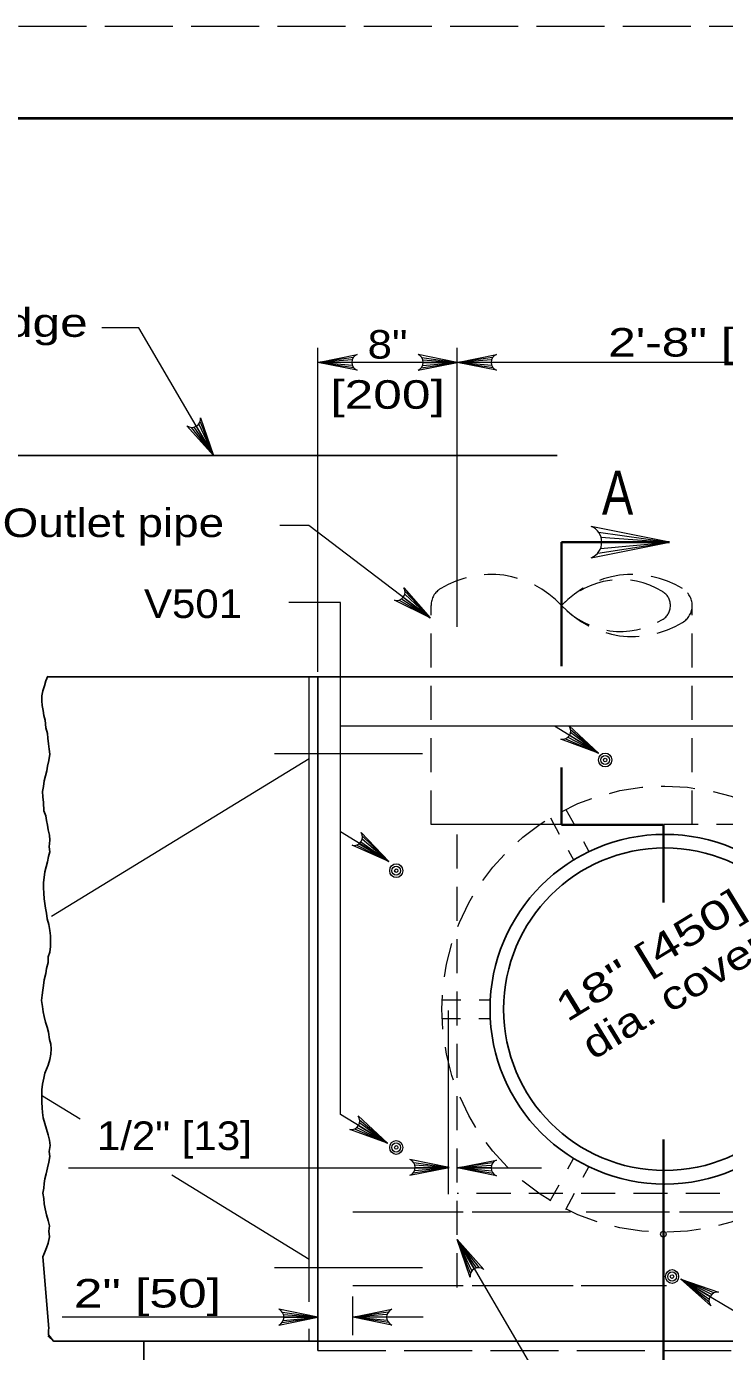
# Model space of a CAD drawing. Extents: x 339.1 to 373.1, y 1412.7 to 1456.7.
# Drawn here: x 343.47 to 347.29, y 1449.51 to 1456.75 of the extents above; entities that cross this region are included whole.
import ezdxf
from ezdxf.enums import TextEntityAlignment as Align

# ---------------------------------------------------------------- set-up
doc = ezdxf.new("R2010")
doc.units = 0
doc.header["$LTSCALE"] = 0.062
doc.header["$PDMODE"] = 32
doc.header["$PDSIZE"] = 0.031
for name, pattern in [('DOTTED', [1.5, 0.3, -1.2]), ('LONG_DASHED', [7.5, 6, -1.5]), ('MEDIUM_DASHED', [4.5, 3, -1.5])]:
    doc.linetypes.add(name, pattern=pattern)
doc.layers.add('1', color=7, linetype='Continuous', lineweight=13)

msp = doc.modelspace()

# ---------------------------------------------------------------- linework, layer by layer
at = {"layer": '1', "lineweight": 25}
for p, q in [((341.0605, 1456.2455), (372.5605, 1456.2455)), ((346.37042, 1454.40183), (342.06367, 1454.40183)), ((345.06217, 1449.51425), (345.06217, 1453.1925)), ((343.55767, 1450.0245), (343.59117, 1449.63442)), ((360.97275, 1449.56467), (343.61608, 1449.56467)), ((344.11025, 1447.75067), (344.11025, 1449.56467))]:
    msp.add_line(p, q, dxfattribs=at)
at = {"layer": '1'}
for p, q in [((345.06217, 1453.22042), (345.06217, 1454.9895)), ((345.25608, 1454.938), (345.06217, 1454.91083)), ((345.62975, 1454.938), (345.82367, 1454.91083)), ((345.82367, 1453.46592), (345.82367, 1454.9895)), ((346.0175, 1454.938), (345.82367, 1454.91083)), ((345.2495, 1454.92458), (345.06217, 1454.91083)), ((345.30475, 1454.91083), (345.06217, 1454.91083)), ((345.2475, 1454.91083), (345.06217, 1454.91083)), ((345.25092, 1454.89342), (345.06217, 1454.91083)), ((345.25833, 1454.88092), (345.06217, 1454.91083)), ((345.82367, 1454.91083), (345.30475, 1454.91083)), ((345.6275, 1454.88092), (345.82367, 1454.91083)), ((345.63492, 1454.89342), (345.82367, 1454.91083)), ((345.63633, 1454.92458), (345.82367, 1454.91083)), ((345.63833, 1454.91083), (345.82367, 1454.91083)), ((346.011, 1454.92458), (345.82367, 1454.91083)), ((347.44108, 1454.91083), (345.82367, 1454.91083)), ((346.009, 1454.91083), (345.82367, 1454.91083)), ((346.01242, 1454.89342), (345.82367, 1454.91083)), ((346.01983, 1454.88092), (345.82367, 1454.91083)), ((344.41067, 1454.5735), (344.491, 1454.40183)), ((344.41775, 1454.58625), (344.491, 1454.40183)), ((344.36967, 1454.55542), (344.491, 1454.40183)), ((344.3845, 1454.55658), (344.491, 1454.40183)), ((344.39742, 1454.56175), (344.491, 1454.40183)), ((346.59217, 1453.86925), (346.9845, 1453.92917)), ((346.59675, 1453.9835), (346.9845, 1453.92917)), ((346.607, 1453.89433), (346.9845, 1453.92917)), ((346.60983, 1453.95658), (346.9845, 1453.92917)), ((346.61383, 1453.92917), (346.9845, 1453.92917)), ((345.52908, 1453.62817), (345.67608, 1453.51533)), ((345.537, 1453.64408), (345.67608, 1453.51533)), ((345.53875, 1453.65858), (345.67608, 1453.51533)), ((345.50575, 1453.61183), (345.67608, 1453.51533)), ((345.51917, 1453.6185), (345.67608, 1453.51533)), ((345.01458, 1449.779), (345.01458, 1453.1925)), ((347.8135, 1452.92358), (345.18583, 1452.92358)), ((346.59558, 1452.77717), (346.35608, 1452.92358)), ((346.44383, 1452.90508), (346.59558, 1452.77717)), ((346.416, 1452.85517), (346.59558, 1452.77717)), ((346.42867, 1452.86317), (346.59558, 1452.77717)), ((346.4375, 1452.87383), (346.59558, 1452.77717)), ((346.44367, 1452.8905), (346.59558, 1452.77717)), ((344.82417, 1452.77517), (345.63325, 1452.77517)), ((345.01458, 1452.74608), (343.60592, 1451.885)), ((345.4495, 1452.18542), (345.18583, 1452.34658)), ((345.27508, 1452.27442), (345.4495, 1452.18542)), ((345.28817, 1452.28167), (345.4495, 1452.18542)), ((345.29767, 1452.29175), (345.4495, 1452.18542)), ((345.30492, 1452.308), (345.4495, 1452.18542)), ((345.306, 1452.3225), (345.4495, 1452.18542)), ((345.77483, 1451.37017), (345.77483, 1450.3675)), ((343.762, 1450.77708), (343.55583, 1450.90317)), ((345.442, 1450.64625), (345.18583, 1450.80292)), ((345.27508, 1450.73225), (345.442, 1450.64625)), ((345.28392, 1450.74292), (345.442, 1450.64625)), ((345.29008, 1450.75958), (345.442, 1450.64625)), ((345.29033, 1450.77417), (345.442, 1450.64625)), ((345.2625, 1450.72425), (345.442, 1450.64625)), ((345.58583, 1450.5405), (345.77975, 1450.51333)), ((345.59242, 1450.52708), (345.77975, 1450.51333)), ((346.0175, 1450.53833), (345.82367, 1450.51125)), ((346.011, 1450.52492), (345.82367, 1450.51125)), ((343.69883, 1450.51125), (345.77608, 1450.51125)), ((345.01458, 1450.01133), (344.26333, 1450.47058)), ((345.58358, 1450.48333), (345.77975, 1450.51333)), ((345.591, 1450.49592), (345.77975, 1450.51333)), ((345.59442, 1450.51333), (345.77975, 1450.51333)), ((345.82367, 1450.51125), (346.28475, 1450.51125)), ((346.009, 1450.51125), (345.82367, 1450.51125)), ((346.01242, 1450.49383), (345.82367, 1450.51125)), ((346.01983, 1450.48125), (345.82367, 1450.51125)), ((345.85683, 1450.27008), (345.2525, 1450.27008)), ((346.44342, 1450.27008), (345.90608, 1450.27008)), ((346.98492, 1450.26933), (346.52825, 1450.26933)), ((347.58933, 1450.26933), (347.03867, 1450.26933)), ((345.91717, 1449.95967), (345.82367, 1450.11967)), ((345.90383, 1449.94792), (345.82367, 1450.11967)), ((345.89675, 1449.93517), (345.82367, 1450.11967)), ((345.93, 1449.96483), (345.82367, 1450.11967)), ((345.94492, 1449.966), (345.82367, 1450.11967)), ((344.82417, 1449.96775), (345.63325, 1449.96775)), ((345.85683, 1449.86692), (345.2525, 1449.86692)), ((346.45683, 1449.86692), (345.90608, 1449.86692)), ((346.96725, 1449.86692), (346.50158, 1449.86692)), ((347.0465, 1449.903), (348.2655, 1449.18067)), ((347.20642, 1449.80933), (347.0465, 1449.903)), ((347.20058, 1449.79258), (347.0465, 1449.903)), ((347.20058, 1449.778), (347.0465, 1449.903)), ((347.21508, 1449.82017), (347.0465, 1449.903)), ((347.2275, 1449.82842), (347.0465, 1449.903)), ((345.2525, 1449.5975), (345.2525, 1449.80892)), ((344.86825, 1449.72275), (345.06217, 1449.69567)), ((345.44642, 1449.72275), (345.2525, 1449.69567)), ((345.06217, 1449.69567), (343.66375, 1449.69567)), ((344.866, 1449.66567), (345.06217, 1449.69567)), ((344.87342, 1449.67825), (345.06217, 1449.69567)), ((344.87483, 1449.70933), (345.06217, 1449.69567)), ((344.87683, 1449.69567), (345.06217, 1449.69567)), ((345.43983, 1449.70933), (345.2525, 1449.69567)), ((345.63683, 1449.69567), (345.2525, 1449.69567)), ((345.43783, 1449.69567), (345.2525, 1449.69567)), ((345.44125, 1449.67825), (345.2525, 1449.69567)), ((345.44867, 1449.66567), (345.2525, 1449.69567)), ((345.01458, 1449.56467), (345.01458, 1449.63208))]:
    msp.add_line(p, q, dxfattribs=at)
at = {"layer": '1', "lineweight": 35}
for p, q in [((346.39475, 1453.92917), (346.9845, 1453.92917)), ((346.39475, 1453.92917), (346.39475, 1453.71192)), ((346.39475, 1453.90008), (346.39475, 1453.71467)), ((346.39475, 1453.87417), (346.39475, 1453.8635)), ((346.39475, 1453.71192), (346.39475, 1453.25158)), ((346.39475, 1452.6985), (346.39475, 1452.38633)), ((346.39475, 1452.38567), (346.95083, 1452.38567)), ((346.95083, 1452.38633), (346.95083, 1451.96)), ((346.95083, 1450.66625), (346.95083, 1450.14908)), ((346.95083, 1450.14908), (346.95083, 1449.00067))]:
    msp.add_line(p, q, dxfattribs=at)
at = {"layer": '1', "linetype": 'MEDIUM_DASHED'}
for p, q in [((345.68083, 1452.38633), (345.68083, 1453.58283)), ((347.10867, 1452.38633), (347.10867, 1453.58283)), ((357.15083, 1452.38633), (345.68083, 1452.38633)), ((346.39475, 1452.38633), (345.68083, 1452.38633)), ((345.82367, 1449.8585), (345.82367, 1452.38633)), ((354.98208, 1450.37083), (345.82367, 1450.37083))]:
    msp.add_line(p, q, dxfattribs=at)
at = {"layer": '1', "linetype": 'DOTTED'}
for p, q in [((346.41842, 1452.46883), (346.54408, 1452.23842)), ((346.33375, 1452.4225), (346.46075, 1452.18975)), ((345.7435, 1451.42825), (346.0055, 1451.42825)), ((345.74217, 1451.3275), (346.00408, 1451.3275)), ((346.33242, 1450.33083), (346.45892, 1450.563)), ((346.41708, 1450.28458), (346.54392, 1450.51717))]:
    msp.add_line(p, q, dxfattribs=at)
at = {"layer": '1', "linetype": 'LONG_DASHED'}
msp.add_line((345.06217, 1449.51425), (357.91233, 1449.51425), dxfattribs=at)
msp.add_lwpolyline([(339.0605, 1434.7455), (373.0605, 1434.7455), (373.0605, 1456.7455), (339.0605, 1456.7455)], close=True, dxfattribs=at)
at = {"layer": '1', "lineweight": 40}
msp.add_lwpolyline([(341.0605, 1456.2455), (372.5605, 1456.2455), (372.5605, 1435.2455), (341.0605, 1435.2455)], close=True, dxfattribs=at)
at = {"layer": '1'}
for points in [[(344.491, 1454.40183), (344.08292, 1455.09875), (343.88075, 1455.09875)], [(345.27633, 1454.868), (345.06217, 1454.91083), (345.27633, 1454.95367)], [(345.6095, 1454.868), (345.82367, 1454.91083), (345.6095, 1454.95367)], [(346.03783, 1454.868), (345.82367, 1454.91083), (346.03783, 1454.95367)], [(344.41975, 1454.60833), (344.491, 1454.40183), (344.34583, 1454.565)], [(345.67608, 1453.51533), (345.01275, 1454.019), (344.85475, 1454.019)], [(346.55617, 1453.8435), (346.9845, 1453.92917), (346.55617, 1454.01492)], [(345.53225, 1453.67975), (345.67608, 1453.51533), (345.48008, 1453.61175)], [(345.18583, 1450.80292), (345.18583, 1453.59867), (344.90242, 1453.59867)], [(346.43525, 1452.92542), (346.59558, 1452.77717), (346.3905, 1452.85233)], [(345.29867, 1452.34342), (345.4495, 1452.18542), (345.2495, 1452.27325)], [(345.28167, 1450.7945), (345.442, 1450.64625), (345.237, 1450.72142)], [(345.56558, 1450.4705), (345.77975, 1450.51333), (345.56558, 1450.55617)], [(346.03783, 1450.46842), (345.82367, 1450.51125), (346.03783, 1450.55408)], [(345.89467, 1449.91317), (345.82367, 1450.11967), (345.96867, 1449.95642)], [(345.82367, 1450.11967), (346.6005, 1448.7935), (346.82142, 1448.7935)], [(347.20967, 1449.75783), (347.0465, 1449.903), (347.25292, 1449.83175)], [(344.848, 1449.65283), (345.06217, 1449.69567), (344.848, 1449.7385)], [(345.46667, 1449.65283), (345.2525, 1449.69567), (345.46667, 1449.7385)]]:
    msp.add_lwpolyline(points, dxfattribs=at)
at = {"layer": '1', "lineweight": 25}
for points in [[(343.58617, 1453.19733), (343.57525, 1453.17158), (343.56758, 1453.1445), (343.55858, 1453.11725), (343.5535, 1453.08883), (343.5535, 1453.06308), (343.55483, 1453.03583), (343.55992, 1453.01), (343.56375, 1452.98292), (343.57142, 1452.95717), (343.57525, 1452.915), (343.583, 1452.88375), (343.5855, 1452.858), (343.58933, 1452.82683), (343.59325, 1452.79833), (343.59583, 1452.77108), (343.59192, 1452.73583), (343.583, 1452.706), (343.58042, 1452.68017), (343.57267, 1452.65167), (343.56633, 1452.62592), (343.56117, 1452.59467), (343.55733, 1452.5675), (343.55858, 1452.53758), (343.56117, 1452.50633), (343.56375, 1452.46158), (343.574, 1452.43442), (343.57917, 1452.40858), (343.58417, 1452.38292), (343.58808, 1452.35708), (343.5945, 1452.32858), (343.59708, 1452.30142), (343.59325, 1452.26483), (343.59583, 1452.23758), (343.58933, 1452.21183), (343.58417, 1452.182), (343.57658, 1452.15617), (343.56892, 1452.129), (343.565, 1452.09642), (343.56242, 1452.06933), (343.56242, 1452.04075), (343.56375, 1452.01083), (343.56633, 1451.981), (343.56892, 1451.95525), (343.57267, 1451.92942), (343.57783, 1451.90233), (343.58175, 1451.87108), (343.59192, 1451.83983), (343.59583, 1451.80858), (343.59967, 1451.77875), (343.59967, 1451.74617), (343.59967, 1451.72042), (343.59583, 1451.68917), (343.58675, 1451.66342), (343.58675, 1451.63217), (343.57917, 1451.60092), (343.574, 1451.57242), (343.565, 1451.53842), (343.56117, 1451.50725), (343.55858, 1451.4815), (343.55483, 1451.45425), (343.55092, 1451.42575), (343.556, 1451.39317), (343.55992, 1451.36333), (343.565, 1451.33758), (343.57267, 1451.30767), (343.58175, 1451.2805), (343.58933, 1451.252), (343.5945, 1451.21258), (343.60217, 1451.18683), (343.6035, 1451.161), (343.60217, 1451.13258), (343.59583, 1451.10267), (343.58675, 1451.07283), (343.56892, 1451.028), (343.56375, 1451.00092), (343.55733, 1450.96833), (343.5535, 1450.93708), (343.5535, 1450.90175), (343.55225, 1450.87058), (343.55483, 1450.83933), (343.556, 1450.8135), (343.55992, 1450.785), (343.56892, 1450.75375), (343.57783, 1450.7225), (343.58808, 1450.69133), (343.5945, 1450.66292), (343.59842, 1450.63292), (343.59325, 1450.60042), (343.59583, 1450.57317), (343.59192, 1450.54208), (343.58417, 1450.51083), (343.57658, 1450.47817), (343.57008, 1450.45108), (343.56633, 1450.42525), (343.56375, 1450.39942), (343.55858, 1450.37233), (343.56375, 1450.34383), (343.56633, 1450.31533), (343.57142, 1450.28675)], [(357.91233, 1449.51425), (357.91233, 1453.1925), (343.58617, 1453.1925)], [(343.57142, 1450.28675), (343.57917, 1450.25425), (343.58808, 1450.22433), (343.5945, 1450.1945), (343.59192, 1450.16467), (343.5945, 1450.13475), (343.58675, 1450.10075), (343.57783, 1450.07367), (343.56758, 1450.0465), (343.55767, 1450.0245)], [(343.59117, 1449.63442), (343.58933, 1449.627), (343.58933, 1449.5985), (343.61608, 1449.56467), (343.58933, 1449.59033), (343.58933, 1449.589)]]:
    msp.add_lwpolyline(points, dxfattribs=at)
at = {"layer": '1', "linetype": 'MEDIUM_DASHED'}
msp.add_circle((346.95836, 1451.37788), 1.21838, dxfattribs=at)
at = {"layer": '1', "lineweight": 25}
for radius in [0.95499, 0.88079]:
    msp.add_circle((346.95836, 1451.37788), radius, dxfattribs=at)
at = {"layer": '1'}
for centre, radius, start, end in [((345.29361, 1454.91092), 0.04623, 112.08782, 247.91395), ((345.59217, 1454.91092), 0.04623, 292.08605, 67.91218), ((346.05511, 1454.91092), 0.04623, 112.08782, 247.91395), ((344.37402, 1454.60156), 0.04623, 232.44128, 8.26741), ((346.52158, 1453.9293), 0.09245, 292.08605, 67.91218), ((345.49245, 1453.65623), 0.04623, 254.57281, 30.39894), ((346.3981, 1452.89784), 0.04623, 260.64591, 36.47204), ((345.25989, 1452.3182), 0.04623, 257.06207, 32.88819), ((345.24453, 1450.76694), 0.04623, 260.64949, 36.47561), ((345.54829, 1450.51339), 0.04623, 292.08605, 67.91218), ((346.05511, 1450.51126), 0.04623, 112.08782, 247.91395), ((345.94045, 1449.91987), 0.04623, 52.3856, 188.21173), ((347.24625, 1449.78608), 0.04623, 81.72821, 217.55434), ((344.83068, 1449.69569), 0.04623, 292.08605, 67.91218), ((345.48399, 1449.69569), 0.04623, 112.08782, 247.91395)]:
    msp.add_arc(centre, radius, start, end, dxfattribs=at)
at = {"layer": '1', "linetype": 'MEDIUM_DASHED'}
for centre, major_axis, ratio, start_param, end_param in [((346.00754, 1453.17289), (0, 0.57976), 0.944544, 5.4977871, 6.806886), ((346.78198, 1453.17289), (0, 0.57976), 0.944544, 5.7594846, 7.0685835), ((346.71735, 1453.24104), (0, 0.48312), 0.944544, 5.7594846, 7.0685835), ((345.78376, 1453.58284), (0, -0.10546), 0.976563, 3.6495066, 4.7123891), ((346.90375, 1453.58266), (0, 0.08788), 0.976563, 3.6503142, 5.7739982), ((347.00567, 1453.58284), (0, 0.10546), 0.976563, 3.6503141, 5.773998), ((346.71735, 1453.92427), (0, -0.48312), 0.944544, 5.4977871, 6.806886), ((346.78198, 1453.99279), (0, -0.57976), 0.944544, 5.4977871, 6.806886)]:
    msp.add_ellipse(centre, major_axis=major_axis, ratio=ratio, start_param=start_param, end_param=end_param, dxfattribs=at)
at = {"layer": '1'}
for centre, major_axis in [((346.63273, 1452.73905), (0, 0.03779)), ((346.63273, 1452.73905), (0, 0.02519)), ((346.63273, 1452.73905), (0, 0.01008)), ((345.49049, 1452.1345), (0, 0.03779)), ((345.49049, 1452.13445), (0, 0.02519)), ((345.49049, 1452.1345), (0, 0.01008)), ((345.49049, 1450.62277), (0, 0.03779)), ((345.49049, 1450.62277), (0, 0.02519)), ((345.49049, 1450.62277), (0, 0.01008)), ((346.99843, 1449.91734), (0, 0.03779)), ((346.99843, 1449.91734), (0, -0.02519)), ((346.99843, 1449.91734), (0, 0.01008))]:
    msp.add_ellipse(centre, major_axis=major_axis, ratio=0.944544, dxfattribs=at)
msp.add_point((346.95083, 1450.14908), dxfattribs=at)

# ---------------------------------------------------------------- texts
for s, height, width, p in [('Lane Edge', 0.156, 1.3, (342.49183, 1455.05033)), ('2\'-8" [800]', 0.156, 1.3, (346.64933, 1454.9425)), ('A', 0.24, 0.8, (346.615, 1454.07875)), ('Outlet pipe', 0.156, 1.2, (343.33858, 1453.95683)), ('V501', 0.156, 1.1, (344.1115, 1453.5145)), ('1/2" [13]', 0.156, 1.1, (343.854, 1450.60875)), ('2" [50]', 0.156, 1.35, (343.72792, 1449.74833))]:
    msp.add_text(s, height=height, dxfattribs=dict(at, width=width)).set_placement(p)
for s, width, p in [('8"', 1.15, (345.44296, 1454.93142)), ('[200]', 1.35, (345.44304, 1454.65742))]:
    msp.add_text(s, height=0.156, dxfattribs=dict(at, width=width)).set_placement(p, align=Align.CENTER)
for s, width, p in [('18" [450]', 1.4, (346.91799, 1451.60621)), ('dia. cover', 1.25, (347.04899, 1451.39186))]:
    msp.add_text(s, height=0.156, rotation=31.435, dxfattribs=dict(at, width=width)).set_placement(p, align=Align.CENTER)

doc.saveas('drawing.dxf')
